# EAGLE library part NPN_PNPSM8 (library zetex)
Dual NPN TRANSISTOR
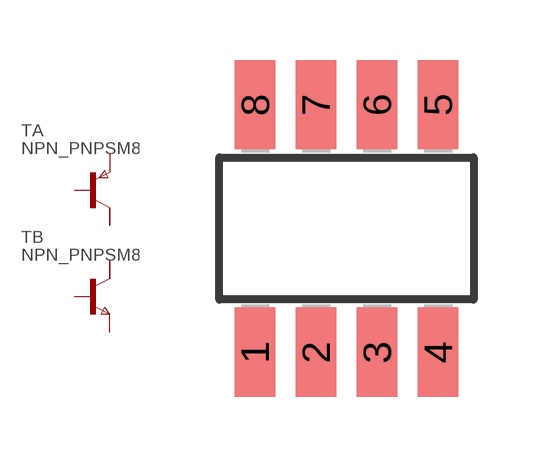
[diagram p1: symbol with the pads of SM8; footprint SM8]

Designator prefix T; gates A=PNP2C B=NPN2C

## NPN_PNPSM8 (OC_FARNELL: unknown; OC_NEWARK: unknown)  [SM8]
1  A:E  pas
2  A:B  pas
3  B:E  pas
4  B:B  pas
5  B:C1  pas
6  B:C2  pas
7  A:C  pas
8  A:C1  pas

## Footprint SM8 (pad centres in mm)
SM8 Package
smd 1.016 x 2.235: 1 -2.286,-3.099; 2 -0.762,-3.099; 3 0.762,-3.099; 4 2.286,-3.099; 5 2.286,3.099; 6 0.762,3.099; 7 -0.762,3.099; 8 -2.286,3.099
